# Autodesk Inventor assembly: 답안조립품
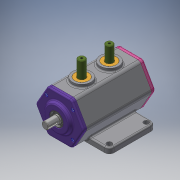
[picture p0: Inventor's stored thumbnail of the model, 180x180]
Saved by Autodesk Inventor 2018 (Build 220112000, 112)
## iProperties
Created: 2021-06
Part Number: 답안조립품
Document SubType Name: Assembly
Designer: 1class 18
Author: 1class 18
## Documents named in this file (11)
- C:\Users\1class 18\Desktop\710606V1041\답안조립품.iam
- C:\Users\1class 18\Desktop\710606V1041\부품1.ipt
- C:\Users\1class 18\Desktop\710606V1041\편심축.ipt
- C:\Users\1class 18\Desktop\710606V1041\베어링 6302.ipt
- C:\Users\1class 18\Desktop\710606V1041\베어링 6203.ipt
- C:\Users\1class 18\Desktop\710606V1041\오일실.ipt
- C:\Users\1class 18\Desktop\710606V1041\앞커버.ipt
- C:\Users\1class 18\Desktop\710606V1041\뒷커버.ipt
- C:\Users\1class 18\Desktop\710606V1041\볼트 M4.ipt
- C:\Users\1class 18\Desktop\710606V1041\부시.ipt
- C:\Users\1class 18\Desktop\710606V1041\슬라이더.ipt
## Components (10 placed, 3 different names)
1. 7-베어링 6203:1
2. 8-오일실:1
3. 9-M4-소켓머리:1
4. 9-M4-소켓머리:2
5. 9-M4-소켓머리:4
6. 9-M4-소켓머리:5
7. 9-M4-소켓머리:6
8. 9-M4-소켓머리:7
9. 9-M4-소켓머리:8
10. 9-M4-소켓머리:9
